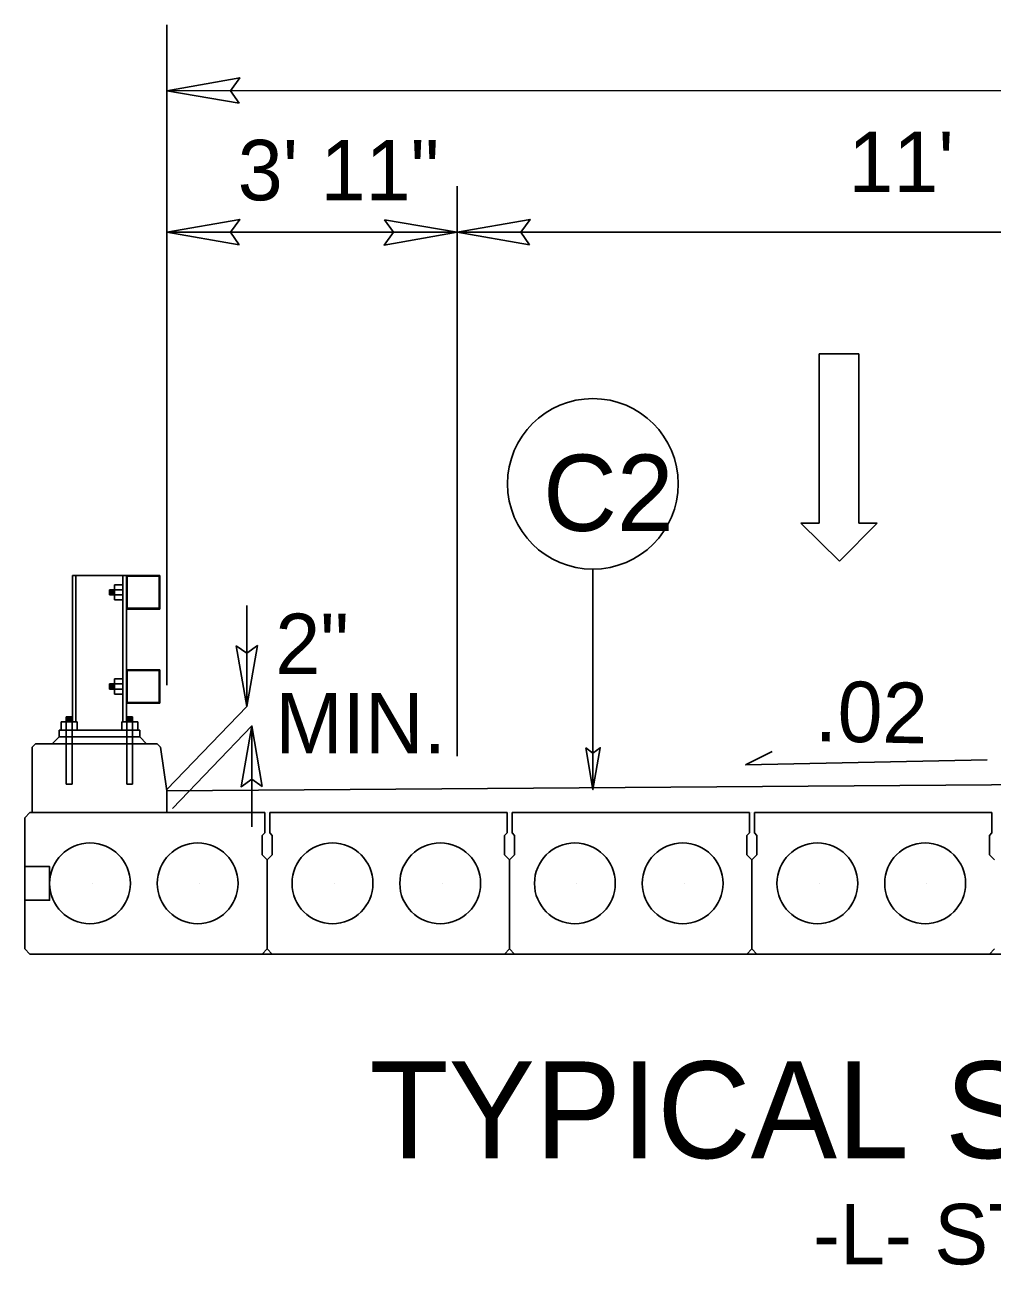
# Model space of a CAD drawing. Extents: x 575722 to 576066, y -53107 to -52774.
# Drawn here: x 575821.77 to 575833.77, y -53077.08 to -53061.7 of the extents above; entities that cross this region are included whole.
import ezdxf

# ---------------------------------------------------------------- set-up
doc = ezdxf.new("R2010")
doc.units = 0
for name, color, linetype in [('Default', 7, 'Continuous'), ('Old_Level_1', 7, 'Continuous'), ('Old_Level_11', 7, 'Continuous'), ('Prop Dimension', 7, 'Continuous'), ('Prop Dimension Text', 7, 'Continuous'), ('Prop DSN Text', 7, 'Continuous'), ('Prop Lane Arrow CELL', 7, 'Continuous'), ('Typical ID Circle CELL', 7, 'Continuous'), ('Typical Pavement Slope CELL', 7, 'Continuous'), ('Typical Terminator CELL', 7, 'Continuous'), ('Typical Text ID Circle CELL', 7, 'Continuous')]:
    doc.layers.add(name, color=color, linetype=linetype)

msp = doc.modelspace()

# ---------------------------------------------------------------- linework, layer by layer
at = {"layer": 'Default'}
for p, q in [((575822.365, -53070.342), (575822.365, -53068.528)), ((575823.033, -53068.528), (575822.365, -53068.528)), ((575822.407, -53070.342), (575822.407, -53068.528)), ((575822.991, -53070.342), (575822.991, -53068.528)), ((575823.033, -53070.342), (575823.033, -53068.528)), ((575823.45, -53068.528), (575823.033, -53068.528)), ((575823.033, -53068.945), (575823.033, -53068.528)), ((575823.44, -53068.538), (575823.043, -53068.538)), ((575823.043, -53068.935), (575823.043, -53068.538)), ((575823.44, -53068.935), (575823.44, -53068.538)), ((575823.45, -53068.945), (575823.45, -53068.528)), ((575822.991, -53068.705), (575822.824, -53068.705)), ((575822.824, -53068.768), (575822.824, -53068.705)), ((575822.991, -53068.768), (575822.824, -53068.768)), ((575822.838, -53068.768), (575822.841, -53068.705)), ((575822.849, -53068.768), (575822.851, -53068.705)), ((575822.859, -53068.768), (575822.861, -53068.705)), ((575822.869, -53068.768), (575822.872, -53068.705)), ((575822.879, -53068.768), (575822.882, -53068.705)), ((575822.886, -53068.831), (575822.886, -53068.643)), ((575822.991, -53068.643), (575822.886, -53068.643)), ((575822.991, -53068.831), (575822.886, -53068.831)), ((575823.44, -53068.935), (575823.043, -53068.935)), ((575823.45, -53068.945), (575823.033, -53068.945)), ((575823.45, -53069.697), (575823.033, -53069.697)), ((575823.033, -53070.114), (575823.033, -53069.697)), ((575823.44, -53069.707), (575823.043, -53069.707)), ((575823.043, -53070.103), (575823.043, -53069.707)), ((575823.44, -53070.103), (575823.44, -53069.707)), ((575823.45, -53070.114), (575823.45, -53069.697)), ((575822.886, -53069.999), (575822.886, -53069.811)), ((575822.991, -53069.811), (575822.886, -53069.811)), ((575822.991, -53069.874), (575822.824, -53069.874)), ((575822.824, -53069.937), (575822.824, -53069.874)), ((575822.991, -53069.937), (575822.824, -53069.937)), ((575822.838, -53069.937), (575822.841, -53069.874)), ((575822.849, -53069.937), (575822.851, -53069.874)), ((575822.859, -53069.937), (575822.861, -53069.874)), ((575822.869, -53069.937), (575822.872, -53069.874)), ((575822.879, -53069.937), (575822.882, -53069.874)), ((575822.991, -53069.999), (575822.886, -53069.999)), ((575823.45, -53070.114), (575823.033, -53070.114)), ((575823.44, -53070.103), (575823.043, -53070.103)), ((575822.287, -53070.448), (575822.287, -53070.281)), ((575822.36, -53070.281), (575822.287, -53070.281)), ((575822.36, -53070.295), (575822.287, -53070.298)), ((575822.36, -53070.305), (575822.287, -53070.308)), ((575822.36, -53070.315), (575822.287, -53070.318)), ((575822.36, -53070.325), (575822.287, -53070.328)), ((575822.36, -53070.448), (575822.36, -53070.281)), ((575823.038, -53070.448), (575823.038, -53070.281)), ((575823.038, -53070.281), (575823.111, -53070.281)), ((575823.038, -53070.295), (575823.111, -53070.298)), ((575823.038, -53070.305), (575823.111, -53070.308)), ((575823.038, -53070.315), (575823.111, -53070.318)), ((575823.038, -53070.325), (575823.111, -53070.328)), ((575823.111, -53070.448), (575823.111, -53070.281)), ((575823.2, -53070.448), (575822.198, -53070.448)), ((575822.198, -53070.531), (575822.198, -53070.448)), ((575822.423, -53070.342), (575822.224, -53070.342)), ((575822.224, -53070.448), (575822.224, -53070.342)), ((575822.36, -53070.336), (575822.287, -53070.339)), ((575822.287, -53071.115), (575822.287, -53070.448)), ((575822.36, -53071.115), (575822.36, -53070.448)), ((575822.423, -53070.448), (575822.423, -53070.342)), ((575822.976, -53070.342), (575823.174, -53070.342)), ((575822.976, -53070.448), (575822.976, -53070.342)), ((575823.038, -53070.336), (575823.111, -53070.339)), ((575823.038, -53071.115), (575823.038, -53070.448)), ((575823.111, -53071.115), (575823.111, -53070.448)), ((575823.174, -53070.448), (575823.174, -53070.342)), ((575823.2, -53070.531), (575823.2, -53070.448)), ((575821.865, -53070.656), (575821.906, -53070.615)), ((575823.415, -53070.615), (575821.906, -53070.615)), ((575822.115, -53070.615), (575822.198, -53070.531)), ((575823.2, -53070.531), (575822.198, -53070.531)), ((575823.283, -53070.615), (575823.2, -53070.531)), ((575823.456, -53070.656), (575823.415, -53070.615)), ((575821.865, -53071.47), (575821.865, -53070.656)), ((575823.534, -53071.199), (575823.456, -53070.656)), ((575822.36, -53071.115), (575822.287, -53071.115)), ((575823.038, -53071.115), (575823.111, -53071.115)), ((575823.534, -53071.47), (575823.534, -53071.199)), ((575821.837, -53071.47), (575821.774, -53071.533)), ((575821.774, -53073.161), (575821.774, -53071.533)), ((575821.837, -53071.47), (575824.749, -53071.47)), ((575823.534, -53071.47), (575821.865, -53071.47)), ((575824.749, -53071.47), (575824.749, -53071.721)), ((575824.781, -53071.47), (575824.781, -53071.47)), ((575824.811, -53071.721), (575824.811, -53071.47)), ((575824.811, -53071.47), (575827.755, -53071.47)), ((575827.755, -53071.47), (575827.755, -53071.721)), ((575827.786, -53071.47), (575827.786, -53071.47)), ((575827.816, -53071.721), (575827.816, -53071.47)), ((575827.816, -53071.47), (575830.76, -53071.47)), ((575830.76, -53071.47), (575830.76, -53071.721)), ((575830.791, -53071.47), (575830.791, -53071.47)), ((575830.822, -53071.721), (575830.822, -53071.47)), ((575830.822, -53071.47), (575833.765, -53071.47)), ((575833.765, -53071.47), (575833.765, -53071.721)), ((575824.749, -53071.721), (575824.718, -53071.752)), ((575824.718, -53071.992), (575824.718, -53071.752)), ((575824.811, -53071.721), (575824.842, -53071.752)), ((575824.842, -53071.752), (575824.842, -53071.992)), ((575827.755, -53071.721), (575827.723, -53071.752)), ((575827.723, -53071.992), (575827.723, -53071.752)), ((575827.816, -53071.721), (575827.847, -53071.752)), ((575827.847, -53071.752), (575827.847, -53071.992)), ((575830.76, -53071.721), (575830.729, -53071.752)), ((575830.729, -53071.992), (575830.729, -53071.752)), ((575830.822, -53071.721), (575830.853, -53071.752)), ((575830.853, -53071.752), (575830.853, -53071.992)), ((575833.765, -53071.721), (575833.734, -53071.752)), ((575833.734, -53071.992), (575833.734, -53071.752)), ((575824.781, -53072.055), (575824.718, -53071.992)), ((575824.779, -53072.055), (575824.842, -53071.992)), ((575827.786, -53072.055), (575827.723, -53071.992)), ((575827.785, -53072.055), (575827.847, -53071.992)), ((575830.791, -53072.055), (575830.729, -53071.992)), ((575830.79, -53072.055), (575830.853, -53071.992)), ((575833.797, -53072.055), (575833.734, -53071.992)), ((575824.779, -53073.161), (575824.779, -53072.055)), ((575824.781, -53073.161), (575824.781, -53072.055)), ((575827.785, -53073.161), (575827.785, -53072.055)), ((575827.786, -53073.161), (575827.786, -53072.055)), ((575830.79, -53073.161), (575830.79, -53072.055)), ((575830.791, -53073.161), (575830.791, -53072.055)), ((575822.609, -53072.347), (575822.609, -53072.347)), ((575823.946, -53072.347), (575823.946, -53072.347)), ((575825.615, -53072.347), (575825.615, -53072.347)), ((575826.951, -53072.347), (575826.951, -53072.347)), ((575828.62, -53072.347), (575828.62, -53072.347)), ((575829.956, -53072.347), (575829.956, -53072.347)), ((575831.625, -53072.347), (575831.625, -53072.347)), ((575832.961, -53072.347), (575832.961, -53072.347)), ((575821.837, -53073.224), (575821.774, -53073.161)), ((575824.718, -53073.224), (575821.837, -53073.224)), ((575854.778, -53073.224), (575821.837, -53073.224)), ((575824.781, -53073.161), (575824.718, -53073.224)), ((575824.842, -53073.224), (575824.779, -53073.161)), ((575827.723, -53073.224), (575824.842, -53073.224)), ((575827.723, -53073.224), (575824.842, -53073.224)), ((575827.786, -53073.161), (575827.723, -53073.224)), ((575827.847, -53073.224), (575827.785, -53073.161)), ((575830.729, -53073.224), (575827.847, -53073.224)), ((575830.729, -53073.224), (575827.847, -53073.224)), ((575830.791, -53073.161), (575830.729, -53073.224)), ((575830.853, -53073.224), (575830.79, -53073.161)), ((575833.734, -53073.224), (575830.853, -53073.224)), ((575833.734, -53073.224), (575830.853, -53073.224)), ((575833.797, -53073.161), (575833.734, -53073.224))]:
    msp.add_line(p, q, dxfattribs=at)
for points in [[(575823.534, -53071.199), (575838.307, -53071.093), (575853.007, -53071.199)], [(575821.774, -53072.139), (575822.081, -53072.139), (575822.081, -53072.556), (575821.774, -53072.556)]]:
    msp.add_lwpolyline(points, dxfattribs=at)
for centre in [(575822.582, -53072.347), (575823.918, -53072.347), (575825.589, -53072.347), (575826.925, -53072.347), (575828.595, -53072.347), (575829.932, -53072.347), (575831.602, -53072.347), (575832.938, -53072.347)]:
    msp.add_circle(centre, 0.501, dxfattribs=at)
at = {"layer": 'Old_Level_11'}
for p, q in [((575823.534, -53069.887), (575823.534, -53061.698)), ((575853.007, -53062.514), (575823.534, -53062.515)), ((575827.134, -53070.769), (575827.134, -53063.698)), ((575827.134, -53064.271), (575823.534, -53064.271)), ((575843.334, -53064.271), (575827.134, -53064.271)), ((575849.407, -53064.271), (575833.207, -53064.271)), ((575823.536, -53071.182), (575824.525, -53070.152)), ((575823.607, -53071.418), (575824.59, -53070.394))]:
    msp.add_line(p, q, dxfattribs=at)
for points in [[(575824.434, -53062.67), (575823.534, -53062.515), (575824.439, -53062.355), (575824.324, -53062.515)], [(575824.434, -53064.426), (575823.534, -53064.271), (575824.439, -53064.111), (575824.324, -53064.271)], [(575826.234, -53064.116), (575827.134, -53064.271), (575826.229, -53064.431), (575826.344, -53064.271)], [(575828.034, -53064.426), (575827.134, -53064.271), (575828.039, -53064.111), (575827.924, -53064.271)]]:
    msp.add_lwpolyline(points, close=True, dxfattribs=at)
at = {"layer": 'Prop Dimension'}
for p, q in [((575824.525, -53068.902), (575824.525, -53070.152)), ((575824.59, -53070.394), (575824.59, -53071.644))]:
    msp.add_line(p, q, dxfattribs=at)
at = {"layer": 'Prop Lane Arrow CELL'}
for p, q in [((575831.622, -53067.879), (575831.622, -53065.779)), ((575831.622, -53065.779), (575832.117, -53065.779)), ((575832.117, -53065.779), (575832.117, -53067.879)), ((575831.877, -53068.351), (575831.397, -53067.879)), ((575831.397, -53067.879), (575831.622, -53067.879)), ((575832.342, -53067.879), (575831.877, -53068.351)), ((575832.117, -53067.879), (575832.342, -53067.879))]:
    msp.add_line(p, q, dxfattribs=at)
at = {"layer": 'Typical ID Circle CELL'}
msp.add_line((575828.818, -53068.45), (575828.818, -53071.184), dxfattribs=at)
msp.add_circle((575828.818, -53067.392), 1.058, dxfattribs=at)
at = {"layer": 'Typical Pavement Slope CELL'}
for p, q in [((575830.709, -53070.878), (575831.043, -53070.712)), ((575833.709, -53070.816), (575830.709, -53070.878))]:
    msp.add_line(p, q, dxfattribs=at)
at = {"layer": 'Typical Terminator CELL'}
for points in [[(575824.396, -53069.403), (575824.525, -53070.152), (575824.659, -53069.398), (575824.525, -53069.494)], [(575824.719, -53071.144), (575824.59, -53070.394), (575824.456, -53071.149), (575824.59, -53071.053)], [(575828.73, -53070.668), (575828.818, -53071.184), (575828.91, -53070.665), (575828.818, -53070.731)]]:
    msp.add_lwpolyline(points, close=True, dxfattribs=at)

# ---------------------------------------------------------------- texts
at = {"layer": 'Old_Level_1'}
msp.add_text('.02', height=0.75, rotation=358.8084, dxfattribs=at).set_placement((575831.567, -53070.584))
at = {"layer": 'Old_Level_11'}
for s, p in [("11'", (575831.986, -53063.773)), ('3\' 11"', (575824.414, -53063.875)), ('2"', (575824.88, -53069.752)), ('MIN.', (575824.88, -53070.735))]:
    msp.add_text(s, height=0.75, rotation=360, dxfattribs=at).set_placement(p)
at = {"layer": 'Prop Dimension Text'}
msp.add_text('TYPICAL SECTION ON STRUCTURE', height=1.2, dxfattribs=at).set_placement((575826.049, -53075.756))
at = {"layer": 'Prop DSN Text'}
msp.add_text('-L- STA. 11+72.38 TO 12+09.63', height=0.75, dxfattribs=at).set_placement((575831.547, -53077.073))
at = {"layer": 'Typical Text ID Circle CELL'}
msp.add_text('C2', height=0.9469, dxfattribs=at).set_placement((575828.201, -53067.976))

doc.saveas('drawing.dxf')
